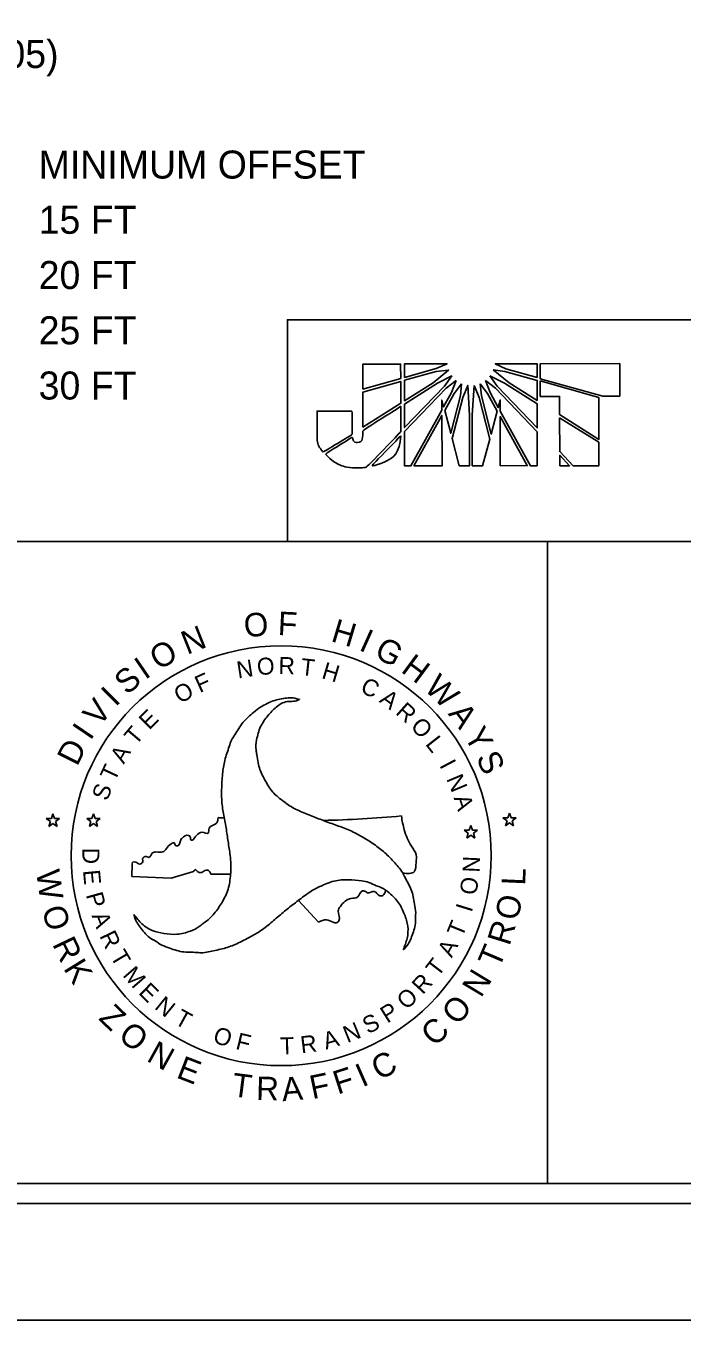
# Model space of a CAD drawing. Extents: x 762655 to 770567, y 650864 to 655190.
# Drawn here: x 763965.1 to 764105.5, y 652778.8 to 653056 of the extents above; entities that cross this region are included whole.
import ezdxf

# ---------------------------------------------------------------- set-up
doc = ezdxf.new("R2010")
doc.units = 0
for name, color, linetype in [('Default', 7, 'Continuous'), ('DEV BORDER CELL', 7, 'Continuous'), ('DEV DOT SWIRL SEAL CELL', 7, 'Continuous'), ('DEV TRANSPORTATION OPERATIONS PLAN SHEET', 7, 'Continuous'), ('Sheet Plan CELL', 7, 'Continuous'), ('Sheet Plot Border Outside CELL', 7, 'Continuous'), ('Text', 7, 'Continuous')]:
    doc.layers.add(name, color=color, linetype=linetype)

msp = doc.modelspace()

# ---------------------------------------------------------------- linework, layer by layer
at = {"layer": 'Default'}
for p, q in [((764045.27, 652983.54), (764037.18, 652983.54)), ((764037.18, 652983.54), (764037.18, 652978.17)), ((764045.28, 652980.42), (764045.27, 652983.54)), ((764055.23, 652983.59), (764046.11, 652983.59)), ((764046.11, 652983.59), (764046.12, 652980.69)), ((764052.9, 652982.56), (764055.23, 652983.59)), ((764074.52, 652983.57), (764065.54, 652983.6)), ((764065.54, 652983.6), (764067.81, 652982.54)), ((764074.52, 652980.66), (764074.52, 652983.57)), ((764092.17, 652983.63), (764075.15, 652983.61)), ((764075.15, 652983.61), (764075.15, 652980.49)), ((764092.17, 652976.65), (764092.17, 652983.63)), ((764046.12, 652980.69), (764052.9, 652982.56)), ((764052.9, 652981.94), (764046.12, 652980.06)), ((764052.2, 652979.53), (764055.55, 652982.26)), ((764055.55, 652982.26), (764052.9, 652981.94)), ((764056.22, 652981), (764053.13, 652979.44)), ((764054.66, 652978.81), (764056.22, 652981)), ((764064.38, 652981.01), (764065.95, 652978.78)), ((764067.51, 652979.45), (764064.38, 652981.01)), ((764065.09, 652982.27), (764068.48, 652979.49)), ((764067.59, 652981.95), (764065.09, 652982.27)), ((764074.52, 652980.04), (764067.59, 652981.95)), ((764067.81, 652982.54), (764074.52, 652980.66)), ((764075.15, 652980.49), (764075.15, 652980.39)), ((764037.18, 652978.17), (764045.28, 652980.42)), ((764045.28, 652979.83), (764037.18, 652977.55)), ((764045.28, 652975.14), (764045.28, 652979.83)), ((764046.12, 652980.06), (764046.12, 652975.68)), ((764046.12, 652975.68), (764052.2, 652979.53)), ((764053.13, 652979.44), (764046.12, 652974.97)), ((764046.13, 652969.92), (764054.66, 652978.81)), ((764055, 652978.37), (764046.13, 652969.06)), ((764057.15, 652980.03), (764055, 652978.37)), ((764056.17, 652977.44), (764057.15, 652980.03)), ((764058.32, 652979.31), (764056.71, 652977.25)), ((764058.09, 652976.81), (764058.32, 652979.31)), ((764059.65, 652978.95), (764058.55, 652976.36)), ((764060.01, 652972.56), (764059.65, 652978.95)), ((764060.99, 652978.95), (764060.58, 652972.56)), ((764062.06, 652976.36), (764060.99, 652978.95)), ((764062.28, 652979.31), (764062.55, 652976.72)), ((764063.85, 652977.26), (764062.28, 652979.31)), ((764063.43, 652980.03), (764064.42, 652977.44)), ((764065.58, 652978.38), (764063.43, 652980.03)), ((764074.48, 652969.01), (764065.58, 652978.38)), ((764065.95, 652978.78), (764074.48, 652969.85)), ((764074.47, 652975.03), (764067.51, 652979.45)), ((764068.48, 652979.49), (764074.47, 652975.76)), ((764074.47, 652975.76), (764074.52, 652980.04)), ((764075.15, 652980.39), (764088.55, 652976.65)), ((764075.15, 652979.91), (764075.15, 652979.86)), ((764087.7, 652976.34), (764075.15, 652979.91)), ((764075.15, 652979.86), (764075.15, 652976.6)), ((764037.18, 652977.55), (764037.19, 652970)), ((764037.19, 652970), (764045.28, 652975.14)), ((764046.12, 652974.97), (764046.13, 652969.92)), ((764054.07, 652973.68), (764054.07, 652975.82)), ((764054.07, 652975.82), (764054.47, 652974.35)), ((764054.47, 652974.35), (764056.17, 652977.44)), ((764056.71, 652977.25), (764054.7, 652973.59)), ((764056, 652968.72), (764058.09, 652976.81)), ((764058.55, 652976.36), (764056.27, 652967.6)), ((764064.39, 652967.48), (764062.06, 652976.36)), ((764062.55, 652976.72), (764064.66, 652968.55)), ((764065.95, 652973.46), (764063.85, 652977.26)), ((764064.42, 652977.44), (764066.16, 652974.22)), ((764066.16, 652974.22), (764066.58, 652975.83)), ((764066.58, 652975.83), (764066.58, 652973.46)), ((764074.48, 652969.85), (764074.47, 652975.03)), ((764075.15, 652976.6), (764079.31, 652976.6)), ((764079.31, 652976.6), (764079.31, 652972.71)), ((764087.71, 652967.4), (764087.7, 652976.34)), ((764088.55, 652976.65), (764092.17, 652976.65)), ((764047.47, 652961.72), (764054.07, 652973.68)), ((764054.07, 652972.52), (764048.1, 652961.72)), ((764054.14, 652961.72), (764054.07, 652972.52)), ((764054.7, 652973.59), (764056, 652968.72)), ((764060.02, 652961.77), (764060.01, 652972.56)), ((764060.58, 652972.56), (764060.59, 652961.77)), ((764064.66, 652968.55), (764065.95, 652973.46)), ((764066.58, 652973.46), (764073.05, 652961.74)), ((764072.39, 652961.78), (764066.58, 652972.3)), ((764066.58, 652972.3), (764066.59, 652961.77)), ((764079.31, 652972.71), (764087.71, 652967.4)), ((764079.31, 652972.05), (764079.32, 652964.8)), ((764087.71, 652966.78), (764079.31, 652972.05)), ((764046.13, 652969.06), (764046.13, 652961.72)), ((764056.27, 652967.6), (764057.8, 652961.77)), ((764062.83, 652961.77), (764064.39, 652967.48)), ((764074.48, 652961.74), (764074.48, 652969.01)), ((764087.71, 652961.75), (764087.71, 652966.78)), ((764079.32, 652964.8), (764082.22, 652961.75)), ((764081.42, 652961.75), (764079.32, 652964.02)), ((764079.32, 652964.02), (764079.32, 652961.75)), ((764046.13, 652961.72), (764047.47, 652961.72)), ((764048.1, 652961.72), (764054.14, 652961.72)), ((764057.8, 652961.77), (764060.02, 652961.77)), ((764060.59, 652961.77), (764062.83, 652961.77)), ((764066.59, 652961.77), (764072.39, 652961.78)), ((764073.05, 652961.74), (764074.48, 652961.74)), ((764079.32, 652961.75), (764081.42, 652961.75)), ((764082.22, 652961.75), (764087.71, 652961.75))]:
    msp.add_line(p, q, dxfattribs=at)
for points in [[(764037.18, 652978.17), (764045.28, 652980.42), (764045.27, 652983.54), (764037.18, 652983.54), (764037.18, 652978.17)], [(764052.9, 652982.56), (764055.23, 652983.59), (764046.11, 652983.59), (764046.12, 652980.69), (764052.9, 652982.56)], [(764067.81, 652982.54), (764074.52, 652980.66), (764074.52, 652983.57), (764065.54, 652983.6), (764067.81, 652982.54)], [(764046.12, 652980.06), (764046.12, 652975.68), (764052.2, 652979.53), (764055.55, 652982.26), (764052.9, 652981.94), (764046.12, 652980.06)], [(764046.12, 652974.97), (764046.13, 652969.92), (764054.66, 652978.81), (764056.22, 652981), (764053.13, 652979.44), (764046.12, 652974.97)], [(764064.38, 652981.01), (764065.95, 652978.78), (764074.48, 652969.85), (764074.47, 652975.03), (764067.51, 652979.45), (764064.38, 652981.01)], [(764065.09, 652982.27), (764068.48, 652979.49), (764074.47, 652975.76), (764074.52, 652980.04), (764067.59, 652981.95), (764065.09, 652982.27)], [(764037.19, 652970), (764045.28, 652975.14), (764045.28, 652979.83), (764037.18, 652977.55), (764037.19, 652970)], [(764057.15, 652980.03), (764055, 652978.37), (764046.13, 652969.06), (764046.13, 652961.72), (764047.47, 652961.72), (764054.07, 652973.68), (764054.07, 652975.82), (764054.47, 652974.35), (764056.17, 652977.44), (764057.15, 652980.03)], [(764058.32, 652979.31), (764056.71, 652977.25), (764054.7, 652973.59), (764056, 652968.72), (764058.09, 652976.81), (764058.32, 652979.31)], [(764058.55, 652976.36), (764056.27, 652967.6), (764057.8, 652961.77), (764060.02, 652961.77), (764060.01, 652972.56), (764059.65, 652978.95), (764058.55, 652976.36)], [(764060.99, 652978.95), (764060.58, 652972.56), (764060.59, 652961.77), (764062.83, 652961.77), (764064.39, 652967.48), (764062.06, 652976.36), (764060.99, 652978.95)], [(764062.28, 652979.31), (764062.55, 652976.72), (764064.66, 652968.55), (764065.95, 652973.46), (764063.85, 652977.26), (764062.28, 652979.31)], [(764063.43, 652980.03), (764064.42, 652977.44), (764066.16, 652974.22), (764066.58, 652975.83), (764066.58, 652973.46), (764073.05, 652961.74), (764074.48, 652961.74), (764074.48, 652969.01), (764065.58, 652978.38), (764063.43, 652980.03)], [(764075.15, 652979.91), (764075.15, 652979.86), (764075.15, 652976.6), (764079.31, 652976.6), (764079.31, 652972.71), (764087.71, 652967.4), (764087.7, 652976.34), (764075.15, 652979.91)], [(764048.1, 652961.72), (764054.14, 652961.72), (764054.07, 652972.52), (764048.1, 652961.72)], [(764066.59, 652961.77), (764072.39, 652961.78), (764066.58, 652972.3), (764066.59, 652961.77)], [(764079.31, 652972.05), (764079.32, 652964.8), (764082.22, 652961.75), (764087.71, 652961.75), (764087.71, 652966.78), (764079.31, 652972.05), (764079.31, 652972.05)], [(764079.32, 652961.75), (764079.32, 652961.75), (764081.42, 652961.75), (764079.32, 652964.02), (764079.32, 652961.75)]]:
    msp.add_lwpolyline(points, dxfattribs=at)
for points in [[(764034.86, 652973.48), (764034.86, 652973.48), (764027.37, 652973.47), (764027.37, 652973.47), (764027.37, 652973.47), (764027.37, 652968.78), (764027.37, 652968.78), (764027.37, 652968.78), (764027.37, 652968.28), (764027.37, 652968.28), (764027.37, 652966.82), (764027.85, 652965.65), (764028.71, 652964.68), (764028.71, 652964.68), (764034.87, 652968.43), (764034.87, 652968.52), (764034.87, 652968.52), (764034.86, 652973.48), (764034.86, 652973.48)], [(764034.86, 652973.48), (764034.86, 652973.48), (764027.37, 652973.47), (764027.37, 652973.47), (764027.37, 652973.47), (764027.37, 652968.78), (764027.37, 652968.78), (764027.37, 652968.78), (764027.37, 652968.28), (764027.37, 652968.28), (764027.37, 652966.82), (764027.85, 652965.65), (764028.71, 652964.68), (764028.71, 652964.68), (764034.87, 652968.43), (764034.87, 652968.52), (764034.87, 652968.52), (764034.86, 652973.48), (764034.86, 652973.48)], [(764036.03, 652966.73), (764035.55, 652966.73), (764035.13, 652967), (764034.96, 652967.89), (764034.96, 652967.89), (764029.15, 652964.29), (764029.15, 652964.29), (764030.94, 652962.41), (764033.8, 652961.29), (764036.22, 652961.29), (764036.85, 652961.29), (764037.33, 652961.35), (764038, 652961.48), (764038, 652961.48), (764045.29, 652969.02), (764045.29, 652969.02), (764045.29, 652969.02), (764045.28, 652974.47), (764045.28, 652974.47), (764045.28, 652974.47), (764037.19, 652969.32), (764037.19, 652969.32), (764037.19, 652967.28), (764036.7, 652966.73), (764036.03, 652966.73)], [(764036.03, 652966.73), (764035.55, 652966.73), (764035.13, 652967), (764034.96, 652967.89), (764034.96, 652967.89), (764029.15, 652964.29), (764029.15, 652964.29), (764030.94, 652962.41), (764033.8, 652961.29), (764036.22, 652961.29), (764036.85, 652961.29), (764037.33, 652961.35), (764038, 652961.48), (764038, 652961.48), (764045.29, 652969.02), (764045.29, 652969.02), (764045.29, 652969.02), (764045.28, 652974.47), (764045.28, 652974.47), (764045.28, 652974.47), (764037.19, 652969.32), (764037.19, 652969.32), (764037.19, 652967.28), (764036.7, 652966.73), (764036.03, 652966.73)], [(764045.29, 652968.17), (764045.29, 652968.17), (764038.99, 652961.66), (764038.99, 652961.66), (764042.07, 652962.42), (764045.14, 652964.47), (764045.29, 652968.17)], [(764045.29, 652968.17), (764045.29, 652968.17), (764038.99, 652961.66), (764038.99, 652961.66), (764042.07, 652962.42), (764045.14, 652964.47), (764045.29, 652968.17)]]:
    msp.add_open_spline(points, degree=3, dxfattribs=at)
at = {"layer": 'DEV BORDER CELL'}
for points in [[(763962.7, 652945.52), (764076.7, 652945.52), (764076.7, 652808.02), (763962.7, 652808.02)], [(764312.7, 652945.52), (764076.7, 652945.52), (764076.7, 652808.02), (764312.7, 652808.02)]]:
    msp.add_lwpolyline(points, close=True, dxfattribs=at)
at = {"layer": 'DEV DOT SWIRL SEAL CELL'}
for p, q in [((763970.84, 652887.19), (763970.52, 652886.19)), ((763971.2, 652886.19), (763970.84, 652887.19)), ((763979.52, 652887.18), (763979.19, 652886.17)), ((763979.88, 652886.17), (763979.52, 652887.18)), ((764068.24, 652886.33), (764067.15, 652886.33)), ((764067.15, 652886.33), (764068.04, 652885.68)), ((764068.56, 652887.33), (764068.24, 652886.33)), ((764068.92, 652886.33), (764068.56, 652887.33)), ((764070.01, 652886.33), (764068.92, 652886.33)), ((764069.12, 652885.68), (764070.01, 652886.33)), ((763969.43, 652886.19), (763970.31, 652885.54)), ((763970.52, 652886.19), (763969.43, 652886.19)), ((763970.31, 652885.54), (763969.99, 652884.5)), ((763969.99, 652884.5), (763970.84, 652885.14)), ((763970.84, 652885.14), (763971.72, 652884.5)), ((763970.84, 652885.14), (763971.72, 652884.5)), ((763972.28, 652886.19), (763971.2, 652886.19)), ((763971.4, 652885.54), (763972.28, 652886.19)), ((763971.4, 652885.54), (763972.28, 652886.19)), ((763971.72, 652884.5), (763971.4, 652885.54)), ((763971.72, 652884.5), (763971.4, 652885.54)), ((763979.19, 652886.17), (763978.11, 652886.17)), ((763978.11, 652886.17), (763978.99, 652885.53)), ((763978.99, 652885.53), (763978.67, 652884.49)), ((763978.67, 652884.49), (763979.52, 652885.13)), ((763979.52, 652885.13), (763980.4, 652884.49)), ((763980.96, 652886.17), (763979.88, 652886.17)), ((763980.08, 652885.53), (763980.96, 652886.17)), ((763980.4, 652884.49), (763980.08, 652885.53)), ((764059.96, 652883.68), (764058.88, 652883.68)), ((764058.88, 652883.68), (764059.76, 652883.04)), ((764060.28, 652884.69), (764059.96, 652883.68)), ((764060.65, 652883.68), (764060.28, 652884.69)), ((764061.73, 652883.68), (764060.65, 652883.68)), ((764060.84, 652883.04), (764061.73, 652883.68)), ((764068.04, 652885.68), (764067.72, 652884.64)), ((764067.72, 652884.64), (764068.56, 652885.28)), ((764068.56, 652885.28), (764069.45, 652884.64)), ((764069.45, 652884.64), (764069.12, 652885.68)), ((764059.76, 652883.04), (764059.44, 652882)), ((764059.44, 652882), (764060.28, 652882.64)), ((764060.28, 652882.64), (764061.17, 652882)), ((764061.17, 652882), (764060.84, 652883.04)), ((763987.76, 652873.74), (763987.84, 652876.4)), ((763996.15, 652873.43), (763987.76, 652873.74)), ((764000.95, 652874.84), (763996.15, 652873.43)), ((764004.66, 652874.28), (764008.87, 652874.24)), ((764023.4, 652868.66), (764027.71, 652863.99))]:
    msp.add_line(p, q, dxfattribs=at)
for start, end in [(265.6785, 265.9762), (271.2035, 275.3236)]:
    msp.add_arc((764023.79, 653118.92), 233.19, start, end, dxfattribs=at)
for points in [[(763988.17, 652865.63), (763989.91, 652863.62), (763992.09, 652862.22), (763994.59, 652861.58), (763997.4, 652861.41), (764000.28, 652862.09), (764002.18, 652863.05), (764002.99, 652863.7), (764004.38, 652864.8), (764005.38, 652865.87), (764007.04, 652868.23), (764008.33, 652871.03), (764008.87, 652874.22), (764008.89, 652874.49), (764008.87, 652877.49), (764008.46, 652880.53), (764008.03, 652883.45), (764007.5, 652886.49), (764007.02, 652889.49), (764006.96, 652892.42), (764007.15, 652895.78), (764007.63, 652898.65), (764008.57, 652901.6), (764009.08, 652903), (764009.78, 652904.13), (764011.52, 652906.78), (764013.81, 652908.93), (764015.31, 652910.06), (764016.73, 652910.81), (764016.97, 652910.94), (764019.82, 652911.85), (764022.61, 652911.96), (764023.55, 652911.72)], [(764023.63, 652911.8), (764023.55, 652911.72), (764020.97, 652911.24), (764018.64, 652910.03), (764016.84, 652908.21), (764015.31, 652905.87), (764014.45, 652903.02), (764014.32, 652900.9), (764014.5, 652899.88), (764014.75, 652898.11), (764015.15, 652896.72), (764016.41, 652894.11), (764018.15, 652891.59), (764020.68, 652889.52), (764020.89, 652889.36), (764023.47, 652887.88), (764026.34, 652886.7), (764029.08, 652885.63), (764031.95, 652884.58), (764034.8, 652883.45), (764037.37, 652882.06), (764040.2, 652880.23), (764042.42, 652878.38), (764044.52, 652876.1), (764045.48, 652874.94), (764046.1, 652873.77), (764047.55, 652870.94), (764048.25, 652867.88), (764048.49, 652866.01), (764048.44, 652864.39), (764048.44, 652864.13), (764047.76, 652861.2), (764046.45, 652858.73), (764045.8, 652858.06)], [(763987.84, 652876.4), (763987.76, 652876.65), (763988.21, 652876.93), (763989.45, 652876.42), (763990.07, 652876.96), (763990.05, 652877.5), (763990.56, 652878.04), (763991.4, 652877.87), (763992.17, 652878.83), (763992.87, 652879.03), (763994.37, 652879.03), (763996.15, 652880.8), (763996.88, 652880.92), (763997.08, 652880.44), (763997.53, 652880.35), (763998.32, 652881.82), (763998.52, 652882.02), (763999.88, 652882.58), (764000.25, 652882.3), (764000.36, 652881.65), (764000.56, 652881.54), (764001.01, 652881.85), (764001.63, 652882.64), (764002.76, 652883.24), (764004.06, 652883.07), (764004.29, 652884.14), (764005.81, 652885.16), (764006.12, 652885.78), (764006.21, 652886.4)], [(764045.73, 652874.51), (764048.2, 652874.81), (764048.57, 652876.77), (764048.59, 652878.4), (764047.58, 652880.3), (764046.05, 652883.77), (764045.43, 652886.74)], [(764004.66, 652874.28), (764004.31, 652874.93), (764003.64, 652875.13), (764002.7, 652874.65), (764002.03, 652874.67), (764001.26, 652875.24), (764000.95, 652874.84)], [(764045.8, 652858.06), (764046.66, 652860.53), (764046.8, 652863.13), (764046.1, 652865.63), (764044.84, 652868.12), (764042.82, 652870.27), (764041.05, 652871.45), (764040.06, 652871.8), (764038.45, 652872.5), (764036.97, 652872.82), (764034.13, 652873.06), (764031.04, 652872.8), (764028.01, 652871.64), (764027.76, 652871.53), (764025.19, 652870.01), (764022.74, 652868.15), (764020.41, 652866.33), (764018.08, 652864.34), (764015.68, 652862.41), (764013.19, 652860.9), (764010.18, 652859.37), (764007.47, 652858.38), (764004.47, 652857.71), (764002.96, 652857.44), (764001.65, 652857.5), (763998.5, 652857.66), (763995.47, 652858.57), (763993.75, 652859.3), (763992.39, 652860.18), (763992.14, 652860.31), (763989.94, 652862.33), (763988.47, 652864.69), (763988.17, 652865.63)], [(764027.71, 652863.99), (764029.41, 652864.5), (764030.82, 652863.96), (764031.5, 652863.85), (764032.07, 652864.27), (764031.89, 652866.4), (764032.38, 652867.38), (764034.67, 652869.08), (764036.08, 652869.39), (764037.12, 652870.69), (764037.55, 652870.66), (764038.19, 652870.29), (764039.64, 652870.58), (764040.79, 652869.64), (764041.47, 652869.7), (764042.02, 652870.76)]]:
    msp.add_spline(points, degree=3, dxfattribs=at)
at = {"layer": 'DEV TRANSPORTATION OPERATIONS PLAN SHEET'}
msp.add_lwpolyline([(764317.85, 653853.76), (762817.85, 653853.76), (762817.85, 652803.75), (764317.85, 652803.75)], close=True, dxfattribs=at)
at = {"layer": 'Sheet Plan CELL'}
msp.add_lwpolyline([(764312.7, 652993.04), (764021.03, 652993.04), (764021.03, 652945.52), (764312.7, 652945.52)], close=True, dxfattribs=at)
at = {"layer": 'Sheet Plot Border Outside CELL'}
msp.add_lwpolyline([(762654.85, 652778.75), (764342.85, 652778.75), (764342.85, 653878.75), (762654.85, 653878.75)], close=True, dxfattribs=at)
at = {"layer": 'Text'}
msp.add_circle((764019.7, 652878.23), 44.97, dxfattribs=at)

# ---------------------------------------------------------------- texts
at = {"layer": 'Default'}
for s, p in [('           OR AS SHOWN IN THE PLANS: (SEE ALSO 1101.05)', (763751.79, 653046.94)), ('MINIMUM OFFSET', (763967.79, 653023.27)), ('15 FT', (763967.79, 653011.44)), ('20 FT', (763967.79, 652999.61)), ('25 FT', (763967.79, 652987.77)), ('30 FT', (763967.79, 652975.94))]:
    msp.add_text(s, height=6, dxfattribs=at).set_placement(p)
at = {"layer": 'DEV DOT SWIRL SEAL CELL'}
for s, height, rotation, p in [('O', 5.04, 5.7649, (764011.96, 652924.96)), ('F', 5.04, 357.2575, (764018.91, 652925.51)), ('H', 5.04, 343.454, (764030.15, 652924.22)), ('N', 5.04, 21.5861, (763999.56, 652921.23)), ('I', 5.04, 335.804, (764036.14, 652922.35)), ('O', 5.04, 30.0935, (763993.45, 652917.85)), ('G', 5.04, 331.5167, (764039.37, 652920.96)), ('I', 5.04, 34.3808, (763990.58, 652915.82)), ('N', 3.63, 9.0227, (764010.48, 652916.17)), ('O', 3.63, 3.9446, (764014.63, 652916.89)), ('R', 3.63, 358.8665, (764019.1, 652917.17)), ('H', 3.63, 343.6322, (764028.18, 652916.3)), ('H', 5.04, 323.4632, (764045.13, 652917.71)), ('S', 5.04, 40.5848, (763986.71, 652912.51)), ('F', 3.63, 24.2569, (764002.26, 652913.05)), ('W', 5.04, 315.8133, (764050.12, 652913.91)), ('I', 5.04, 44.8722, (763984.25, 652909.99)), ('O', 3.63, 29.335, (763998.05, 652910.7)), ('C', 3.63, 333.4761, (764036.41, 652913.39)), ('V', 5.04, 51.5806, (763980.81, 652905.69)), ('A', 3.63, 323.3199, (764040.51, 652911.26)), ('E', 3.63, 44.5692, (763991.44, 652905.02)), ('R', 3.63, 318.2418, (764044, 652908.71)), ('A', 5.04, 306.7762, (764055.3, 652908.61)), ('I', 5.04, 55.8679, (763978.88, 652902.74)), ('T', 3.63, 49.6473, (763988.58, 652901.71)), ('O', 3.63, 313.1637, (764047.21, 652905.79)), ('Y', 5.04, 299.7484, (764058.72, 652903.97)), ('D', 5.04, 63.459, (763976.03, 652897.21)), ('L', 3.63, 308.0856, (764050.43, 652902.12)), ('A', 3.63, 59.8035, (763986.02, 652897.72)), ('S', 5.04, 293.2249, (764061.36, 652899.31)), ('T', 3.63, 64.8816, (763984.08, 652893.93)), ('I', 3.63, 297.9295, (764053.48, 652897.61)), ('N', 3.63, 292.8514, (764054.99, 652894.71)), ('S', 3.63, 69.9597, (763982.49, 652889.79)), ('A', 3.63, 287.7733, (764056.59, 652890.65)), ('D', 3.63, 270.272, (763977.15, 652879.93)), ('N', 3.63, 87.733, (764062.15, 652874.57)), ('E', 3.63, 275.3501, (763977.27, 652875.07)), ('O', 3.63, 82.9269, (764061.52, 652869.7)), ('P', 3.63, 285.5063, (763977.87, 652869.87)), ('I', 3.63, 72.7707, (764060.44, 652865.94)), ('A', 3.63, 290.5843, (763979.07, 652865.41)), ('T', 3.63, 67.6926, (764058.44, 652860.55)), ('R', 3.63, 295.6624, (763980.74, 652861.07)), ('A', 3.63, 62.6145, (764056.21, 652856.21)), ('T', 3.63, 300.7405, (763983.02, 652856.67)), ('T', 3.63, 52.4584, (764053.26, 652852.07)), ('M', 3.63, 310.8967, (763985.64, 652852.57)), ('E', 3.63, 315.9748, (763988.98, 652848.75)), ('R', 3.63, 47.3803, (764050, 652848.33)), ('N', 3.63, 321.0529, (763992.4, 652845.59)), ('O', 3.63, 42.3022, (764046.48, 652845.07)), ('T', 3.63, 331.209, (763996.64, 652842.35)), ('P', 3.63, 32.146, (764042.4, 652842.24)), ('N', 3.63, 21.9899, (764033.86, 652838.06)), ('S', 3.63, 27.068, (764038.27, 652839.94)), ('O', 3.63, 341.3652, (764004.86, 652838.33)), ('F', 3.63, 346.4433, (764009.78, 652836.86)), ('T', 3.63, 1.6775, (764019.54, 652835.66)), ('R', 3.63, 6.7556, (764024.03, 652835.9)), ('A', 3.63, 16.9118, (764029.28, 652836.67))]:
    msp.add_text(s, height=height, rotation=rotation, dxfattribs=at).set_placement(p)
at = {"layer": 'Text'}
for s, height, rotation, p in [('T', 3.63, 353.7884, (764023.73, 652916.94)), ('W', 5.04, 278.15, (763967.22, 652874.86)), ('L', 5.04, 87.429, (764071.9, 652871.78)), ('O', 5.04, 78.9896, (764070.39, 652864.19)), ('O', 5.04, 287.1147, (763968.38, 652866.72)), ('R', 5.04, 72.7519, (764068.56, 652858.76)), ('R', 5.04, 295.5541, (763970.63, 652859.31)), ('T', 5.04, 66.881, (764066.32, 652853.87)), ('K', 5.04, 301.7918, (763972.98, 652854.09)), ('N', 5.04, 58.892, (764062.48, 652847.63)), ('O', 5.04, 50.4526, (764057.52, 652841.68)), ('Z', 5.04, 316.1688, (763980.43, 652843.24)), ('O', 5.04, 322.5233, (763984.55, 652839.11)), ('C', 5.04, 43.0807, (764052.52, 652837.13)), ('N', 5.04, 330.9626, (763990.67, 652834.38)), ('E', 5.04, 338.9517, (763997.04, 652830.77)), ('I', 5.04, 23.7503, (764037.07, 652828.58)), ('C', 5.04, 28.0033, (764040.7, 652830.01)), ('T', 5.04, 352.6948, (764008.97, 652826.74)), ('R', 5.04, 358.5656, (764014.29, 652825.91)), ('A', 5.04, 4.8034, (764020.01, 652825.63)), ('F', 5.04, 11.7751, (764026.39, 652826.06)), ('F', 5.04, 17.7627, (764031.79, 652827.04))]:
    msp.add_text(s, height=height, rotation=rotation, dxfattribs=at).set_placement(p)

doc.saveas('drawing.dxf')
